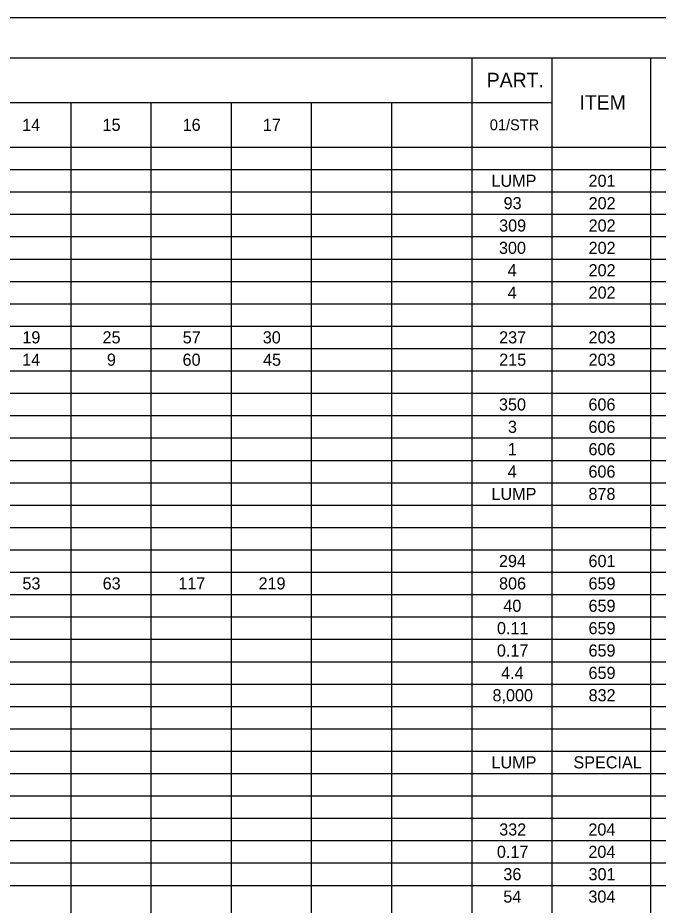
# Model space of a CAD drawing. Extents: x 0 to 34, y 0 to 22.
# Drawn here: x 8.87 to 16.9, y 10.89 to 22 of the extents above; entities that cross this region are included whole.
import ezdxf

# ---------------------------------------------------------------- set-up
doc = ezdxf.new("R2010")
doc.units = 0
for name, color, linetype in [('SH_Border', 7, 'Continuous'), ('SH_Cut_Line', 7, 'Continuous'), ('SH_Text', 7, 'Continuous')]:
    doc.layers.add(name, color=color, linetype=linetype)

msp = doc.modelspace()

# ---------------------------------------------------------------- linework, layer by layer
at = {"layer": 'SH_Border'}
msp.add_lwpolyline([(1.5, 21.5), (33.5, 21.5), (33.5, 0.5), (1.5, 0.5)], close=True, dxfattribs=at)
at = {"layer": 'SH_Cut_Line'}
msp.add_lwpolyline([(0, 0), (34, 0), (34, 22), (0, 22)], close=True, dxfattribs=at)
at = {"layer": 'SH_Text'}
for p, q in [((1.5, 21.5), (32, 21.5)), ((14.56, 21.5), (14.56, 0.5)), ((15.564, 21.5), (15.564, 0.5)), ((16.799, 21.5), (16.799, 0.5)), ((1.5, 20.94), (15.564, 20.94)), ((9.537, 20.94), (9.537, 0.5)), ((10.541, 20.94), (10.541, 0.5)), ((11.546, 20.94), (11.546, 0.5)), ((12.55, 20.94), (12.55, 0.5)), ((13.555, 20.94), (13.555, 0.5)), ((1.5, 20.38), (32, 20.38)), ((1.5, 20.1), (32, 20.1)), ((1.5, 19.82), (32, 19.82)), ((1.5, 19.54), (32, 19.54)), ((1.5, 19.26), (32, 19.26)), ((1.5, 18.98), (32, 18.98)), ((1.5, 18.7), (32, 18.7)), ((1.5, 18.42), (32, 18.42)), ((1.5, 18.14), (32, 18.14)), ((1.5, 17.86), (32, 17.86)), ((1.5, 17.58), (32, 17.58)), ((1.5, 17.3), (32, 17.3)), ((1.5, 17.02), (32, 17.02)), ((1.5, 16.74), (32, 16.74)), ((1.5, 16.46), (32, 16.46)), ((1.5, 16.18), (32, 16.18)), ((1.5, 15.9), (32, 15.9)), ((1.5, 15.62), (32, 15.62)), ((1.5, 15.34), (32, 15.34)), ((1.5, 15.06), (32, 15.06)), ((1.5, 14.78), (32, 14.78)), ((1.5, 14.5), (32, 14.5)), ((1.5, 14.22), (32, 14.22)), ((1.5, 13.94), (32, 13.94)), ((1.5, 13.66), (32, 13.66)), ((1.5, 13.38), (32, 13.38)), ((1.5, 13.1), (32, 13.1)), ((1.5, 12.82), (32, 12.82)), ((1.5, 12.54), (32, 12.54)), ((1.5, 12.26), (32, 12.26)), ((1.5, 11.98), (32, 11.98)), ((1.5, 11.7), (32, 11.7)), ((1.5, 11.42), (32, 11.42)), ((1.5, 11.14), (32, 11.14))]:
    msp.add_line(p, q, dxfattribs=at)

# ---------------------------------------------------------------- texts
for s, height, p in [('PART.', 0.1818, (14.749, 21.129)), ('ITEM', 0.1818, (15.91, 20.849)), ('14', 0.1515, (8.929, 20.584)), ('15', 0.1515, (9.936, 20.584)), ('16', 0.1515, (10.939, 20.584)), ('17', 0.1515, (11.944, 20.584)), ('01/STR', 0.1364, (14.787, 20.592)), ('LUMP', 0.1515, (14.808, 19.884)), ('201', 0.1515, (16.024, 19.884)), ('93', 0.1515, (14.96, 19.604)), ('202', 0.1515, (16.025, 19.604)), ('309', 0.1515, (14.904, 19.324)), ('202', 0.1515, (16.025, 19.324)), ('300', 0.1515, (14.902, 19.044)), ('202', 0.1515, (16.025, 19.044)), ('4', 0.152, (15.011, 18.764)), ('202', 0.1515, (16.025, 18.764)), ('4', 0.152, (15.011, 18.484)), ('202', 0.1515, (16.025, 18.484)), ('19', 0.1515, (8.931, 17.924)), ('25', 0.1515, (9.936, 17.924)), ('57', 0.1515, (10.94, 17.924)), ('30', 0.1515, (11.943, 17.924)), ('237', 0.1515, (14.904, 17.924)), ('203', 0.1515, (16.025, 17.924)), ('14', 0.1515, (8.929, 17.644)), ('9', 0.152, (9.99, 17.644)), ('60', 0.1515, (10.938, 17.644)), ('45', 0.1515, (11.946, 17.644)), ('215', 0.1515, (14.905, 17.644)), ('203', 0.1515, (16.025, 17.644)), ('350', 0.1515, (14.902, 17.084)), ('606', 0.1515, (16.023, 17.084)), ('3', 0.152, (15.014, 16.804)), ('606', 0.1515, (16.023, 16.804)), ('1', 0.152, (15.013, 16.524)), ('606', 0.1515, (16.023, 16.524)), ('4', 0.152, (15.011, 16.244)), ('606', 0.1515, (16.023, 16.244)), ('LUMP', 0.1515, (14.808, 15.964)), ('878', 0.1515, (16.023, 15.964)), ('294', 0.1515, (14.902, 15.124)), ('601', 0.1515, (16.024, 15.124)), ('53', 0.1515, (8.932, 14.844)), ('63', 0.1515, (9.937, 14.844)), ('219', 0.1515, (11.89, 14.844)), ('806', 0.1515, (14.903, 14.844)), ('659', 0.1515, (16.024, 14.844)), ('117', 0.1515, (10.885, 14.844)), ('40', 0.1515, (14.957, 14.564)), ('659', 0.1515, (16.024, 14.564)), ('0.11', 0.1515, (14.877, 14.284)), ('659', 0.1515, (16.024, 14.284)), ('0.17', 0.1515, (14.876, 14.004)), ('659', 0.1515, (16.024, 14.004)), ('4.4', 0.1515, (14.929, 13.724)), ('659', 0.1515, (16.024, 13.724)), ('8,000', 0.1515, (14.821, 13.444)), ('832', 0.1515, (16.025, 13.444)), ('LUMP', 0.1515, (14.808, 12.604)), ('SPECIAL', 0.1515, (15.835, 12.604)), ('332', 0.1515, (14.905, 11.764)), ('204', 0.1515, (16.022, 11.764)), ('0.17', 0.1515, (14.876, 11.484)), ('204', 0.1515, (16.022, 11.484)), ('36', 0.1515, (14.957, 11.204)), ('301', 0.1515, (16.024, 11.204)), ('54', 0.1515, (14.956, 10.924)), ('304', 0.1515, (16.022, 10.924))]:
    msp.add_text(s, height=height, dxfattribs=at).set_placement(p)

doc.saveas('drawing.dxf')
